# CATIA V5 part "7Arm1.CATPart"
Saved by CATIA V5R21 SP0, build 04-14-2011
Part number: Arm1
Bounding box of the stored display mesh (mm): x -25 to 11, y 73.3 to 108.28, z 135.805 to 383.305
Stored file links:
  F:\教程\Robotic_Arm_Arduino_Kinect\机械臂CAD\Arm_Detailed_Design\Arm1.CATPart
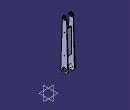
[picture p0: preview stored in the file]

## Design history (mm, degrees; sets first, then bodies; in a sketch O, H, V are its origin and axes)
Body1 (main body)
  DatumSurface1
  DatumSurface2
  Sketch1 on face of DatumSurface1, origin (-22, 0, 0), H (0, -1, 0), V (0, 0, 1)
    arc A1 centre (-90.79, 153.3046) radius 17.5 from (-108.2798, 153.9012) to (-73.3002, 153.9012) ccw
    point P1 (-90.79, 153.3046)
    arc A2 centre (-90.79, 373.3046) radius 10 from (-80.7958, 373.6456) to (-100.7842, 373.6456) ccw
    point P2 (-90.79, 373.3046)
    line L1 (-80.7958, 373.6456) -> (-73.3002, 153.9012)
    line L2 (-100.7842, 373.6456) -> (-108.2798, 153.9012)
    axis line L3 (-90.79, 373.3046) -> (-90.79, 153.3046)
    construction circle A3 centre (-90.79, 153.3046) radius 12.25
    circle A4 centre (-90.79, 161.8046) radius 1.25
    point P7 (-90.79, 161.8046)
    circle A5 centre (-90.79, 313.3046) radius 1.25
    point P8 (-90.79, 313.3046)
    circle A6 centre (-90.79, 213.3046) radius 1.25
    point P9 (-90.79, 213.3046)
    circle A7 centre (-90.79, 373.3046) radius 7
    circle A8 centre (-99.29, 153.3046) radius 1.25
    circle A9 centre (-90.79, 144.8046) radius 1.25
    circle A10 centre (-82.29, 153.3046) radius 1.25
    radius A1 = 17.5
    radius A2 = 10
    distance P2 P1 = 220
    radius A3 = 12.25
    radius A4 = 1.25
    distance P7 P1 = 8.5
    radius A5 = 1.25
    distance P8 P2 = 60
    radius A6 = 1.25
    distance P9 P8 = 100
    radius A7 = 7
    tangency: L1 A2, L1 A1, L2 A2, L2 A1
    vertical: L3 V
    coincidence: P7 L3, P8 L3, P9 L3
  Pad1: profile Sketch1, direction (-1, 0, 0), length 3
Body2
  DatumSurface3
  DatumCurve1
  DatumSurface4 to DatumSurface6
  Sketch2 on DatumSurface6, origin (11, 0, 0), H (0, -1, 0), V (0, 0, 1)
    arc A1 centre (-90.79, 153.3046) radius 17.5 from (-108.2798, 153.9012) to (-73.3002, 153.9012) ccw
    point P1 (-90.79, 153.3046)
    arc A2 centre (-90.79, 373.3046) radius 10 from (-80.7958, 373.6456) to (-100.7842, 373.6456) ccw
    point P2 (-90.79, 373.3046)
    axis line L1 (-90.79, 431.4654) -> (-90.79, 58.352)
    line L2 (-100.7842, 373.6456) -> (-108.2798, 153.9012)
    line L3 (-80.7958, 373.6456) -> (-73.3002, 153.9012)
    reference projected arc E1 centre (-90.79, 153.3046) radius 26.8116 from (-70.2512, 136.0705) to (-111.3288, 170.5388) ccw from edge of DatumCurve1
    circle A3 centre (-90.79, 153.3046) radius 10.5
    circle A4 centre (-90.79, 313.3046) radius 1.25
    point P9 (-90.79, 313.3046)
    circle A5 centre (-90.79, 213.3046) radius 1.25
    point P10 (-90.79, 213.3046)
    point P11 (-90.79, 228.3046)
    point P12 (-90.79, 303.3046)
    circle A6 centre (-90.79, 373.3046) radius 7
    radius A1 = 17.5
    radius A2 = 10
    distance P1 P2 = 220
    radius A3 = 10.5
    distance P9 P2 = 60
    distance P9 P10 = 100
    radius A4 = 1.25
    radius A5 = 1.25
    radius A6 = 7
    vertical: L1 V
    coincidence: P2 L1, P1 L1, P9 L1, P10 L1, L1 P11, L1 P12
    tangency: L2 A1, L2 A2, L3 A2, L3 A1
    concentricity: A1 E1
  Pad2: profile Sketch2, direction (-1, 0, 0), length 3
Body3
  Sketch3 on end face of Pad2, origin (8, 0, 0), H (0, -1, 0), V (0, 0, 1)
    line L1 (-92.79, 323.3046) -> (-88.79, 323.3046)
    line L2 (-88.79, 323.3046) -> (-88.79, 203.3046)
    line L3 (-88.79, 203.3046) -> (-92.79, 203.3046)
    line L4 (-92.79, 203.3046) -> (-92.79, 323.3046)
    reference projected circle E1 centre (-90.79, 213.3046) radius 1.25 from edge [end face of Pad1 | face of Pad1 from Sketch1.A6]
    reference projected circle E2 centre (-90.79, 213.3046) radius 1.25 from edge [end face of Pad1 | face of Pad1 from Sketch1.A6]
    length L1 = 4
    length L2 = 120
    distance L2 E1 = 0.75
    distance L3 E2 = 8.75
    horizontal: L1 H, L3 H
    vertical: L2 V, L4 V
  Pad3: profile Sketch3, direction (-1, 0, 0), up to start face of Pad1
